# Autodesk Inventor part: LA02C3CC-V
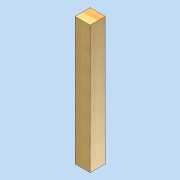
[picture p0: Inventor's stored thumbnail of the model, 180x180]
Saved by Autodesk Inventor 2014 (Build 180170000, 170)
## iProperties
Created: 2011-04
Part Number: LA02C3CC-V
Document SubType Name: Modeling
Designer: david.appleford
Density: 0.44 g/cm^3
Description: Lug Corner 0.5w 3 Slots
Cost Center: £6.00
Mass: 1169.87 g
Surface Area: 1656.48 cm^2
Volume: 2658.8 cm^3
Material: 000 Redwood
Appearance: Wood (Pine)
Justset: False
Author: david.appleford
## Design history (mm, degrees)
sketch "Sketch1"
  geometry: L1 (0, 0)-(68, 0); L2 (68, 0)-(68, 68); L3 (68, 68)-(0, 68); L4 (0, 68)-(0, 0)
  constraints: 8 end point, 2 parallel, 1 horizontal, 1 perpendicular
  dimensions: "d0" = 68 distance between parallel lines of L2 L4 (= t); "d1" = 68 distance between parallel lines of L1 L3 (= t)
extrude "Extrusion1" new body sketch "Sketch1" distance "d2" = 575 (= -0.5 x Cl + 0.5 x w - 0.5 x t); taper "d3" = 0 deg
body "Solid1"
other parameters: "t" = 68 [user parameter; used in 3 equation terms], "Cl" = 2 [user parameter; used in 1 equation term]
